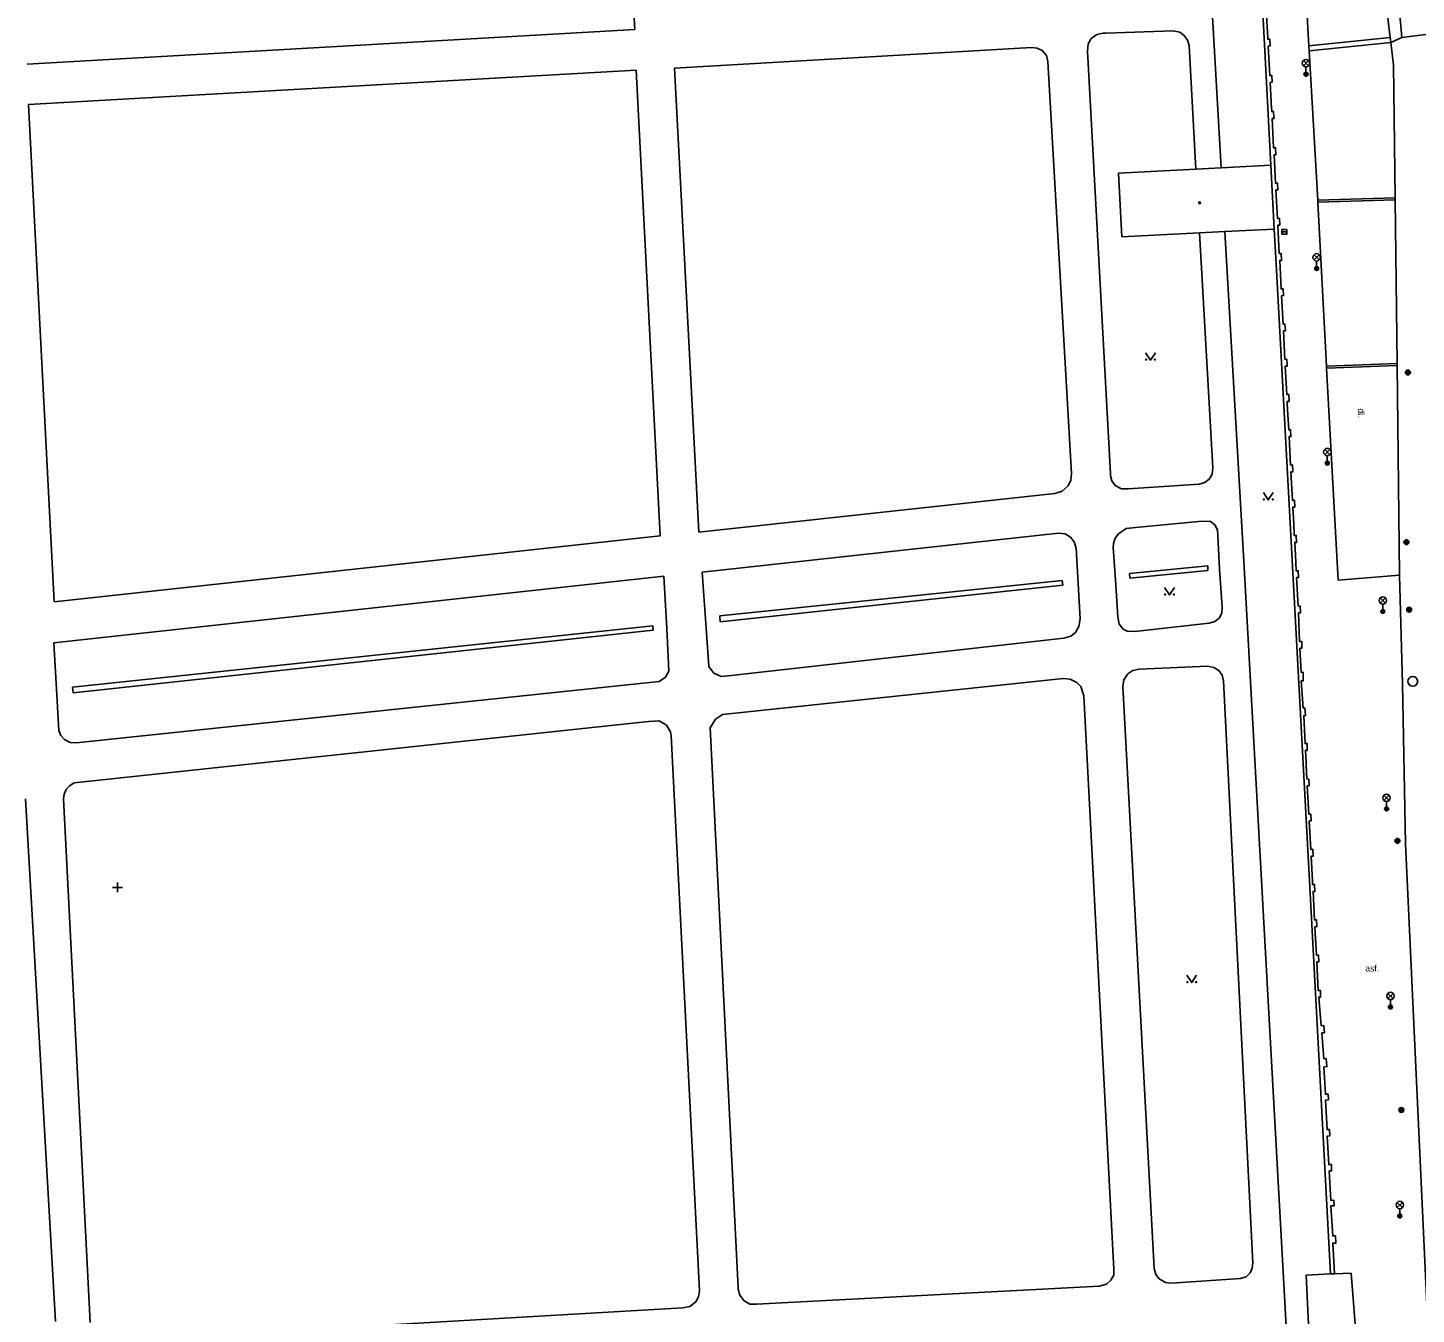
# Model space of a CAD drawing. Extents: x -599951 to -598963, y -1164095 to -1162939.
# Drawn here: x -599354.1 to -599212.4, y -1163560.6 to -1163429.4 of the extents above; entities that cross this region are included whole.
import ezdxf

# ---------------------------------------------------------------- set-up
doc = ezdxf.new("R2010")
doc.units = 0
for name, color, linetype in [('Level 11', 7, 'Continuous'), ('Level 25', 7, 'Continuous'), ('Level 27', 7, 'Continuous'), ('Level 33', 7, 'Continuous'), ('Level 36', 7, 'Continuous'), ('Level 39', 7, 'Continuous'), ('Level 40', 7, 'Continuous'), ('Level 5', 7, 'Continuous'), ('Level 51', 7, 'Continuous'), ('Level 54', 7, 'Continuous'), ('Level 7', 7, 'Continuous')]:
    doc.layers.add(name, color=color, linetype=linetype)

msp = doc.modelspace()

# ---------------------------------------------------------------- linework, layer by layer
at = {"layer": 'Level 11'}
for points in [[(-599223.37, -1163431.24), (-599224.17, -1163417.06)], [(-599216.79, -1163416.18), (-599215.08, -1163430.4)], [(-599213.89, -1163430.39), (-599214.27, -1163426.13)], [(-599227.73, -1163427.58), (-599227.58, -1163430.43), (-599227.57, -1163430.57), (-599227.37, -1163430.56), (-599227.33, -1163431.26), (-599227.53, -1163431.27), (-599227.37, -1163434.27), (-599227.17, -1163434.26), (-599227.13, -1163434.95), (-599227.33, -1163434.97), (-599227.22, -1163436.94), (-599227.22, -1163437.1), (-599227.17, -1163437.96), (-599226.98, -1163437.95), (-599226.95, -1163438.49), (-599226.94, -1163438.65), (-599227.14, -1163438.66), (-599226.98, -1163441.66), (-599226.78, -1163441.65), (-599226.74, -1163442.35), (-599226.94, -1163442.35), (-599226.79, -1163445.25), (-599226.59, -1163445.24), (-599226.55, -1163445.94), (-599226.75, -1163445.95), (-599226.59, -1163448.85), (-599226.39, -1163448.84), (-599226.36, -1163449.53), (-599226.56, -1163449.54), (-599226.4, -1163452.44), (-599226.2, -1163452.43), (-599226.16, -1163453.13), (-599226.36, -1163453.14), (-599226.21, -1163456), (-599226.21, -1163456.04), (-599226.01, -1163456.02), (-599225.97, -1163456.72), (-599226.17, -1163456.73), (-599226.02, -1163459.63), (-599225.82, -1163459.62), (-599225.78, -1163460.32), (-599225.98, -1163460.33), (-599225.83, -1163463.23), (-599225.63, -1163463.21), (-599225.6, -1163463.75), (-599225.59, -1163463.91), (-599225.79, -1163463.93), (-599225.63, -1163466.82), (-599225.43, -1163466.81), (-599225.4, -1163467.51), (-599225.6, -1163467.52), (-599225.59, -1163467.78), (-599225.44, -1163470.41), (-599225.24, -1163470.4), (-599225.21, -1163471.1), (-599225.4, -1163471.11), (-599225.25, -1163474.01), (-599225.05, -1163474), (-599225.01, -1163474.7), (-599225.21, -1163474.71), (-599225.06, -1163477.6), (-599224.86, -1163477.6), (-599224.82, -1163478.29), (-599225.02, -1163478.3), (-599224.93, -1163480), (-599224.87, -1163481.2), (-599224.67, -1163481.19), (-599224.63, -1163481.89), (-599224.83, -1163481.9), (-599224.76, -1163483.17), (-599224.67, -1163484.8), (-599224.47, -1163484.78), (-599224.44, -1163485.48), (-599224.64, -1163485.49), (-599224.48, -1163488.39), (-599224.28, -1163488.38), (-599224.24, -1163489.08), (-599224.44, -1163489.09), (-599224.34, -1163492), (-599224.11, -1163491.99), (-599224.09, -1163492.68), (-599224.3, -1163492.69), (-599224.18, -1163495.15), (-599223.98, -1163495.12), (-599223.95, -1163496.03), (-599224.16, -1163496.03), (-599223.98, -1163498.8), (-599223.78, -1163498.78), (-599223.72, -1163499.56), (-599223.91, -1163499.57), (-599223.77, -1163502.42), (-599223.57, -1163502.41), (-599223.54, -1163503.11), (-599223.73, -1163503.12), (-599223.67, -1163504.27), (-599223.66, -1163504.57), (-599223.58, -1163506.02), (-599223.39, -1163506.04), (-599223.34, -1163506.71), (-599223.54, -1163506.72), (-599223.39, -1163509.61), (-599223.19, -1163509.6), (-599223.15, -1163510.3), (-599223.35, -1163510.31), (-599223.19, -1163513.21), (-599222.99, -1163513.2), (-599222.96, -1163513.9), (-599223.16, -1163513.91), (-599223.09, -1163515.17), (-599223.02, -1163516.45), (-599223, -1163516.8), (-599222.8, -1163516.79), (-599222.76, -1163517.49), (-599222.96, -1163517.5), (-599222.81, -1163520.4), (-599222.61, -1163520.39), (-599222.57, -1163521.08), (-599222.77, -1163521.1), (-599222.61, -1163523.99), (-599222.41, -1163523.98), (-599222.38, -1163524.68), (-599222.58, -1163524.69), (-599222.42, -1163527.59), (-599222.21, -1163527.59), (-599222.18, -1163528.27), (-599222.38, -1163528.29), (-599222.3, -1163529.13), (-599222.12, -1163531.2), (-599221.87, -1163531.17), (-599221.8, -1163531.91), (-599222.05, -1163531.93), (-599221.87, -1163534.57), (-599221.62, -1163534.55), (-599221.55, -1163535.36), (-599221.84, -1163535.39), (-599221.69, -1163538.18), (-599221.42, -1163538.17), (-599221.39, -1163538.74), (-599221.67, -1163538.78), (-599221.52, -1163541.78), (-599221.29, -1163541.78), (-599221.26, -1163542.44), (-599221.52, -1163542.46), (-599221.36, -1163545.35), (-599221.09, -1163545.36), (-599221.06, -1163546.01), (-599221.31, -1163546.01), (-599221.21, -1163547.83), (-599221.2, -1163547.87), (-599221.14, -1163549.01), (-599220.82, -1163549), (-599220.8, -1163549.56), (-599221.14, -1163549.56), (-599220.94, -1163552.64), (-599220.65, -1163552.64), (-599220.62, -1163553.37), (-599220.94, -1163553.37), (-599220.77, -1163556.49)], [(-599213.89, -1163430.39), (-599206.06, -1163429.41)], [(-599223.37, -1163431.24), (-599215.08, -1163430.4)], [(-599223.34, -1163431.74), (-599223.37, -1163431.24)], [(-599215.02, -1163430.9), (-599223.34, -1163431.74)], [(-599215.08, -1163430.4), (-599215.02, -1163430.9)], [(-599213.89, -1163430.39), (-599215.02, -1163430.9)], [(-599215.02, -1163430.9), (-599214.74, -1163433.2), (-599214.58, -1163446.74)], [(-599222.48, -1163446.98), (-599223.34, -1163431.74)], [(-599222.48, -1163446.98), (-599214.58, -1163446.74)], [(-599214.58, -1163446.74), (-599214.58, -1163446.94)], [(-599222.47, -1163447.18), (-599222.48, -1163446.98)], [(-599214.58, -1163446.94), (-599222.47, -1163447.18)], [(-599221.58, -1163463.92), (-599222.47, -1163447.18)], [(-599214.58, -1163446.94), (-599214.38, -1163463.66)], [(-599221.58, -1163463.92), (-599214.38, -1163463.66)], [(-599221.57, -1163464.12), (-599221.58, -1163463.92)], [(-599214.38, -1163463.86), (-599221.57, -1163464.12)], [(-599214.38, -1163463.66), (-599214.38, -1163463.86)], [(-599214.38, -1163463.86), (-599214.13, -1163485.25)], [(-599220.38, -1163485.75), (-599221.57, -1163464.12)], [(-599220.38, -1163485.75), (-599214.13, -1163485.25)], [(-599206.17, -1163653.7), (-599209.8, -1163593.38), (-599213.54, -1163512.63), (-599213.84, -1163496.33), (-599214.13, -1163485.25)], [(-599220.77, -1163556.49), (-599219.08, -1163556.44), (-599214.58, -1163613.69), (-599219.43, -1163613.78)]]:
    msp.add_lwpolyline(points, dxfattribs=at)
at = {"layer": 'Level 25'}
for centre, radius in [((-599213.28, -1163464.56), 0.25), ((-599213.28, -1163464.56), 0.2), ((-599213.28, -1163464.56), 0.15), ((-599213.28, -1163464.56), 0.1), ((-599213.28, -1163464.56), 0.05), ((-599213.43, -1163481.87), 0.25), ((-599213.43, -1163481.87), 0.2), ((-599213.43, -1163481.87), 0.15), ((-599213.43, -1163481.87), 0.1), ((-599213.43, -1163481.87), 0.05), ((-599213.15, -1163488.75), 0.25), ((-599213.15, -1163488.75), 0.2), ((-599213.15, -1163488.75), 0.15), ((-599213.15, -1163488.75), 0.1), ((-599213.15, -1163488.75), 0.05), ((-599214.35, -1163512.34), 0.25), ((-599214.35, -1163512.34), 0.2), ((-599214.35, -1163512.34), 0.15), ((-599214.35, -1163512.34), 0.1), ((-599214.35, -1163512.34), 0.05), ((-599213.95, -1163539.79), 0.25), ((-599213.95, -1163539.79), 0.2), ((-599213.95, -1163539.79), 0.15), ((-599213.95, -1163539.79), 0.1), ((-599213.95, -1163539.79), 0.05)]:
    msp.add_circle(centre, radius, dxfattribs=at)
at = {"layer": 'Level 27'}
msp.add_line((-599226.14, -1163450.22), (-599225.64, -1163450.22), dxfattribs=at)
msp.add_lwpolyline([(-599226.14, -1163450.47), (-599225.64, -1163450.47), (-599225.64, -1163449.97), (-599226.14, -1163449.97)], close=True, dxfattribs=at)
msp.add_circle((-599212.78, -1163496.07), 0.5, dxfattribs=at)
at = {"layer": 'Level 33'}
for p, q in [((-599223.94, -1163433.28), (-599223.41, -1163432.75)), ((-599223.94, -1163432.75), (-599223.41, -1163433.28)), ((-599223.68, -1163433.39), (-599223.68, -1163434.14)), ((-599222.85, -1163453.09), (-599222.32, -1163452.56)), ((-599222.85, -1163452.56), (-599222.32, -1163453.09)), ((-599222.59, -1163453.2), (-599222.59, -1163453.95)), ((-599221.77, -1163472.95), (-599221.23, -1163472.42)), ((-599221.77, -1163472.42), (-599221.23, -1163472.95)), ((-599221.5, -1163473.06), (-599221.5, -1163473.81)), ((-599216.1, -1163488.08), (-599215.57, -1163487.55)), ((-599216.1, -1163487.55), (-599215.57, -1163488.08)), ((-599215.84, -1163488.19), (-599215.84, -1163488.94)), ((-599215.73, -1163508.22), (-599215.2, -1163507.69)), ((-599215.73, -1163507.69), (-599215.2, -1163508.22)), ((-599215.46, -1163508.33), (-599215.46, -1163509.08)), ((-599215.32, -1163528.42), (-599214.79, -1163527.89)), ((-599215.32, -1163527.89), (-599214.79, -1163528.42)), ((-599215.06, -1163528.53), (-599215.06, -1163529.28)), ((-599214.37, -1163549.74), (-599213.84, -1163549.21)), ((-599214.37, -1163549.21), (-599213.84, -1163549.74)), ((-599214.11, -1163549.85), (-599214.11, -1163550.6))]:
    msp.add_line(p, q, dxfattribs=at)
for centre, radius in [((-599223.68, -1163433.02), 0.375), ((-599223.68, -1163434.14), 0.2), ((-599223.68, -1163434.14), 0.145), ((-599223.68, -1163434.14), 0.0876), ((-599222.59, -1163452.82), 0.375), ((-599222.59, -1163453.95), 0.2), ((-599222.59, -1163453.95), 0.145), ((-599222.59, -1163453.95), 0.0876), ((-599221.5, -1163472.68), 0.375), ((-599221.5, -1163473.81), 0.2), ((-599221.5, -1163473.81), 0.145), ((-599221.5, -1163473.81), 0.0876), ((-599215.84, -1163487.82), 0.375), ((-599215.84, -1163488.94), 0.2), ((-599215.84, -1163488.94), 0.145), ((-599215.84, -1163488.94), 0.0876), ((-599215.46, -1163507.95), 0.375), ((-599215.46, -1163509.08), 0.2), ((-599215.46, -1163509.08), 0.145), ((-599215.46, -1163509.08), 0.0876), ((-599215.06, -1163528.16), 0.375), ((-599215.06, -1163529.28), 0.2), ((-599215.06, -1163529.28), 0.145), ((-599215.06, -1163529.28), 0.0876), ((-599214.11, -1163549.48), 0.375), ((-599214.11, -1163550.6), 0.2), ((-599214.11, -1163550.6), 0.145), ((-599214.11, -1163550.6), 0.0876)]:
    msp.add_circle(centre, radius, dxfattribs=at)
at = {"layer": 'Level 36'}
for p, q in [((-599345.43, -1163517.08), (-599344.43, -1163517.08)), ((-599344.93, -1163517.58), (-599344.93, -1163516.58))]:
    msp.add_line(p, q, dxfattribs=at)
for points in [[(-599240.04, -1163462.55), (-599239.54, -1163463.3), (-599239.04, -1163462.55)], [(-599228.02, -1163476.81), (-599227.52, -1163477.56), (-599227.02, -1163476.81)], [(-599238.1, -1163486.51), (-599237.6, -1163487.26), (-599237.1, -1163486.51)], [(-599235.83, -1163526.04), (-599235.33, -1163526.79), (-599234.83, -1163526.04)]]:
    msp.add_lwpolyline(points, dxfattribs=at)
for centre in [(-599239.99, -1163463.25), (-599239.09, -1163463.25), (-599227.97, -1163477.51), (-599227.07, -1163477.51), (-599238.05, -1163487.21), (-599237.15, -1163487.21), (-599235.78, -1163526.74), (-599234.88, -1163526.74)]:
    msp.add_circle(centre, 0.05, dxfattribs=at)
at = {"layer": 'Level 39'}
for radius in [0.09, 0.0398]:
    msp.add_circle((-599234.53, -1163447.25), radius, dxfattribs=at)
at = {"layer": 'Level 5'}
for points in [[(-599234.9, -1163443.82), (-599242.79, -1163444.23)], [(-599232.32, -1163443.68), (-599234.9, -1163443.82)], [(-599227.25, -1163443.42), (-599232.32, -1163443.68)], [(-599226.91, -1163449.93), (-599227.25, -1163443.42)], [(-599242.79, -1163444.23), (-599242.45, -1163450.74)], [(-599242.45, -1163450.74), (-599234.54, -1163450.33)], [(-599234.54, -1163450.33), (-599231.95, -1163450.19)], [(-599231.95, -1163450.19), (-599226.91, -1163449.93)]]:
    msp.add_lwpolyline(points, dxfattribs=at)
at = {"layer": 'Level 51'}
for points in [[(-599283.44, -1163489.99), (-599248.5, -1163486.26)], [(-599349.44, -1163497.25), (-599290.28, -1163490.84)]]:
    msp.add_lwpolyline(points, dxfattribs=at)
at = {"layer": 'Level 54'}
for points in [[(-599295.5, -1163369.28), (-599292.15, -1163429.58)], [(-599232.32, -1163443.68), (-599235.18, -1163393.79)], [(-599227.25, -1163443.42), (-599228.36, -1163422.66)], [(-599292.15, -1163429.58), (-599354.14, -1163433.13)], [(-599237.24, -1163429.72), (-599244.11, -1163429.97)], [(-599236.56, -1163429.86), (-599237.24, -1163429.72)], [(-599236.09, -1163430.18), (-599236.56, -1163429.86)], [(-599245.91, -1163431.05), (-599245.98, -1163431.8)], [(-599245.58, -1163430.51), (-599245.91, -1163431.05)], [(-599245.03, -1163430.1), (-599245.58, -1163430.51)], [(-599244.4, -1163429.95), (-599245.03, -1163430.1)], [(-599244.11, -1163429.97), (-599244.4, -1163429.95)], [(-599235.75, -1163430.66), (-599236.09, -1163430.18)], [(-599235.61, -1163431.2), (-599235.75, -1163430.66)], [(-599234.9, -1163443.82), (-599235.61, -1163431.2)], [(-599288.09, -1163433.54), (-599251.67, -1163431.4)], [(-599251.67, -1163431.4), (-599251.1, -1163431.47)], [(-599251.1, -1163431.47), (-599250.59, -1163431.71)], [(-599250.59, -1163431.71), (-599250.16, -1163432.23)], [(-599250.16, -1163432.23), (-599250.01, -1163432.83)], [(-599245.98, -1163431.8), (-599243.62, -1163474.91)], [(-599354.02, -1163437.24), (-599292, -1163433.72)], [(-599292, -1163433.72), (-599289.55, -1163481.21)], [(-599285.61, -1163480.85), (-599288.09, -1163433.54)], [(-599250.01, -1163432.83), (-599247.61, -1163474.86)], [(-599351.39, -1163487.95), (-599354.02, -1163437.24)], [(-599233.19, -1163474.28), (-599234.54, -1163450.33)], [(-599229.99, -1163484.42), (-599231.95, -1163450.19)], [(-599226.72, -1163453.49), (-599226.91, -1163449.93)], [(-599223.33, -1163516.41), (-599226.72, -1163453.49)], [(-599247.61, -1163474.86), (-599247.66, -1163475.54)], [(-599243.62, -1163474.91), (-599243.62, -1163475.09)], [(-599243.62, -1163475.09), (-599243.47, -1163475.6)], [(-599233.54, -1163475.43), (-599233.24, -1163474.92)], [(-599233.24, -1163474.92), (-599233.19, -1163474.28)], [(-599248.54, -1163476.68), (-599249.29, -1163476.9)], [(-599247.94, -1163476.13), (-599248.54, -1163476.68)], [(-599247.66, -1163475.54), (-599247.94, -1163476.13)], [(-599243.47, -1163475.6), (-599243.15, -1163476.1)], [(-599243.15, -1163476.1), (-599242.5, -1163476.43)], [(-599242.5, -1163476.43), (-599241.83, -1163476.43)], [(-599241.83, -1163476.43), (-599234.58, -1163475.97)], [(-599234.58, -1163475.97), (-599233.99, -1163475.8)], [(-599233.99, -1163475.8), (-599233.54, -1163475.43)], [(-599249.29, -1163476.9), (-599285.61, -1163480.85)], [(-599242.03, -1163480.47), (-599242.8, -1163481.01)], [(-599241.06, -1163480.36), (-599242.03, -1163480.47)], [(-599234.28, -1163479.74), (-599241.06, -1163480.36)], [(-599233.42, -1163479.77), (-599234.28, -1163479.74)], [(-599232.98, -1163480.09), (-599233.42, -1163479.77)], [(-599232.72, -1163480.63), (-599232.98, -1163480.09)], [(-599232.67, -1163481.2), (-599232.72, -1163480.63)], [(-599289.55, -1163481.21), (-599351.39, -1163487.95)], [(-599248.91, -1163480.94), (-599285.27, -1163484.92)], [(-599248.26, -1163481.01), (-599248.91, -1163480.94)], [(-599247.71, -1163481.35), (-599248.26, -1163481.01)], [(-599247.33, -1163481.85), (-599247.71, -1163481.35)], [(-599247.14, -1163482.47), (-599247.33, -1163481.85)], [(-599243.31, -1163482.01), (-599243.35, -1163482.4)], [(-599243.13, -1163481.48), (-599243.31, -1163482.01)], [(-599242.8, -1163481.01), (-599243.13, -1163481.48)], [(-599232.49, -1163484.63), (-599232.67, -1163481.2)], [(-599247.14, -1163482.47), (-599246.73, -1163489.7)], [(-599243.35, -1163482.4), (-599243.12, -1163485.7)], [(-599285.27, -1163484.92), (-599284.9, -1163490.18)], [(-599241.67, -1163485.06), (-599233.69, -1163484.28)], [(-599241.66, -1163485.53), (-599241.67, -1163485.06)], [(-599241.66, -1163485.53), (-599233.69, -1163484.77)], [(-599233.69, -1163484.28), (-599233.69, -1163484.77)], [(-599232.24, -1163488.51), (-599232.49, -1163484.63)], [(-599229.99, -1163484.42), (-599226.22, -1163552.63)], [(-599351.43, -1163492.15), (-599289.2, -1163485.35)], [(-599289.2, -1163485.35), (-599288.9, -1163490.68)], [(-599248.56, -1163485.77), (-599283.47, -1163489.39)], [(-599248.5, -1163486.26), (-599248.56, -1163485.77)], [(-599243.12, -1163485.7), (-599242.86, -1163489.48)], [(-599283.47, -1163489.39), (-599283.44, -1163489.99)], [(-599232.53, -1163489.61), (-599232.26, -1163489.1)], [(-599232.26, -1163489.1), (-599232.24, -1163488.51)], [(-599349.53, -1163496.67), (-599290.32, -1163490.39)], [(-599290.32, -1163490.39), (-599290.28, -1163490.84)], [(-599288.9, -1163490.68), (-599288.67, -1163495.02)], [(-599284.9, -1163490.18), (-599284.6, -1163494.55)], [(-599247.2, -1163491.07), (-599246.85, -1163490.48)], [(-599246.85, -1163490.48), (-599246.73, -1163489.7)], [(-599242.86, -1163489.48), (-599242.72, -1163490.22)], [(-599242.72, -1163490.22), (-599242.33, -1163490.74)], [(-599242.33, -1163490.74), (-599241.93, -1163490.96)], [(-599241.13, -1163490.99), (-599233.55, -1163490.12)], [(-599233.55, -1163490.12), (-599232.96, -1163489.97)], [(-599232.96, -1163489.97), (-599232.53, -1163489.61)], [(-599351.13, -1163497.47), (-599351.43, -1163492.15)], [(-599282.31, -1163495.47), (-599248.38, -1163491.66)], [(-599248.38, -1163491.66), (-599247.68, -1163491.47)], [(-599247.68, -1163491.47), (-599247.2, -1163491.07)], [(-599241.93, -1163490.96), (-599241.13, -1163490.99)], [(-599288.67, -1163495.02), (-599289.03, -1163495.64)], [(-599284.6, -1163494.55), (-599284.08, -1163495.24)], [(-599241.84, -1163495.3), (-599241.33, -1163494.96)], [(-599241.33, -1163494.96), (-599240.7, -1163494.82)], [(-599240.7, -1163494.82), (-599233.68, -1163494.53)], [(-599233.68, -1163494.53), (-599233.07, -1163494.65)], [(-599233.07, -1163494.65), (-599232.56, -1163494.97)], [(-599232.56, -1163494.97), (-599232.22, -1163495.44)], [(-599289.67, -1163496.08), (-599349.15, -1163502.33)], [(-599289.03, -1163495.64), (-599289.67, -1163496.08)], [(-599284.08, -1163495.24), (-599283.34, -1163495.58)], [(-599283.34, -1163495.58), (-599282.31, -1163495.47)], [(-599283.2, -1163499.45), (-599248.44, -1163495.79)], [(-599248.44, -1163495.79), (-599247.72, -1163495.84)], [(-599247.72, -1163495.84), (-599247.06, -1163496.18)], [(-599247.06, -1163496.18), (-599246.64, -1163496.6)], [(-599242.35, -1163496.61), (-599242.26, -1163495.9)], [(-599242.26, -1163495.9), (-599241.84, -1163495.3)], [(-599232.22, -1163495.44), (-599232.08, -1163496.01)], [(-599232.08, -1163496.01), (-599229.1, -1163555.37)], [(-599350.9, -1163501.07), (-599351.13, -1163497.47)], [(-599349.44, -1163497.25), (-599349.53, -1163496.67)], [(-599246.64, -1163496.6), (-599246.35, -1163497.55)], [(-599246.35, -1163497.55), (-599243.28, -1163556.03)], [(-599239.17, -1163555.97), (-599242.35, -1163496.61)], [(-599349.35, -1163506.43), (-599290.75, -1163500.15)], [(-599290.75, -1163500.15), (-599289.65, -1163500.1)], [(-599289.65, -1163500.1), (-599288.93, -1163500.53)], [(-599288.93, -1163500.53), (-599288.51, -1163501.22)], [(-599284.45, -1163500.82), (-599283.91, -1163499.91)], [(-599283.91, -1163499.91), (-599283.2, -1163499.45)], [(-599350.7, -1163501.59), (-599350.9, -1163501.07)], [(-599350.34, -1163502), (-599350.7, -1163501.59)], [(-599349.75, -1163502.29), (-599350.34, -1163502)], [(-599288.51, -1163501.22), (-599288.43, -1163501.64)], [(-599288.43, -1163501.64), (-599285.54, -1163558.23)], [(-599281.59, -1163557.9), (-599284.45, -1163500.82)], [(-599349.15, -1163502.33), (-599349.75, -1163502.29)], [(-599350.45, -1163508.06), (-599350.35, -1163507.57)], [(-599350.35, -1163507.57), (-599350.15, -1163507.1)], [(-599350.15, -1163507.1), (-599349.81, -1163506.74)], [(-599349.81, -1163506.74), (-599349.35, -1163506.43)], [(-599354.31, -1163508.04), (-599351.26, -1163561.37)], [(-599347.71, -1163561.46), (-599350.45, -1163508.06)], [(-599221.17, -1163556.51), (-599223.33, -1163516.41)], [(-599222.7, -1163615.97), (-599226.22, -1163552.63)], [(-599239.17, -1163555.97), (-599239, -1163556.58)], [(-599229.38, -1163556.4), (-599229.17, -1163555.91)], [(-599229.17, -1163555.91), (-599229.1, -1163555.37)], [(-599244.03, -1163557.57), (-599243.59, -1163557.16)], [(-599243.59, -1163557.16), (-599243.29, -1163556.64)], [(-599243.29, -1163556.64), (-599243.28, -1163556.03)], [(-599239, -1163556.58), (-599238.66, -1163557.02)], [(-599238.66, -1163557.02), (-599238.02, -1163557.4)], [(-599238.02, -1163557.4), (-599237.4, -1163557.44)], [(-599237.4, -1163557.44), (-599230.36, -1163556.99)], [(-599230.36, -1163556.99), (-599229.79, -1163556.79)], [(-599229.79, -1163556.79), (-599229.38, -1163556.4)], [(-599285.66, -1163558.85), (-599285.54, -1163558.23)], [(-599281.59, -1163557.9), (-599281.59, -1163558.06)], [(-599281.59, -1163558.06), (-599281.43, -1163558.68)], [(-599281.43, -1163558.68), (-599280.98, -1163559.25)], [(-599279.72, -1163559.59), (-599244.76, -1163557.76)], [(-599244.76, -1163557.76), (-599244.03, -1163557.57)], [(-599345.9, -1163563.36), (-599287.26, -1163559.98)], [(-599287.26, -1163559.98), (-599286.52, -1163559.83)], [(-599286.52, -1163559.83), (-599285.92, -1163559.35)], [(-599285.92, -1163559.35), (-599285.66, -1163558.85)], [(-599280.98, -1163559.25), (-599280.41, -1163559.58)], [(-599280.41, -1163559.58), (-599279.72, -1163559.59)]]:
    msp.add_lwpolyline(points, dxfattribs=at)
at = {"layer": 'Level 7'}
for points in [[(-599221.17, -1163556.51), (-599223.67, -1163556.64), (-599222.71, -1163576.75)], [(-599220.77, -1163556.49), (-599221.17, -1163556.51)]]:
    msp.add_lwpolyline(points, dxfattribs=at)

# ---------------------------------------------------------------- texts
at = {"layer": 'Level 40'}
msp.add_text('dl.', height=0.65, rotation=271.97, dxfattribs=at).set_placement((-599218.38, -1163468.24))
msp.add_text('asf.', height=0.65, dxfattribs=at).set_placement((-599217.62, -1163525.66))

doc.saveas('drawing.dxf')
